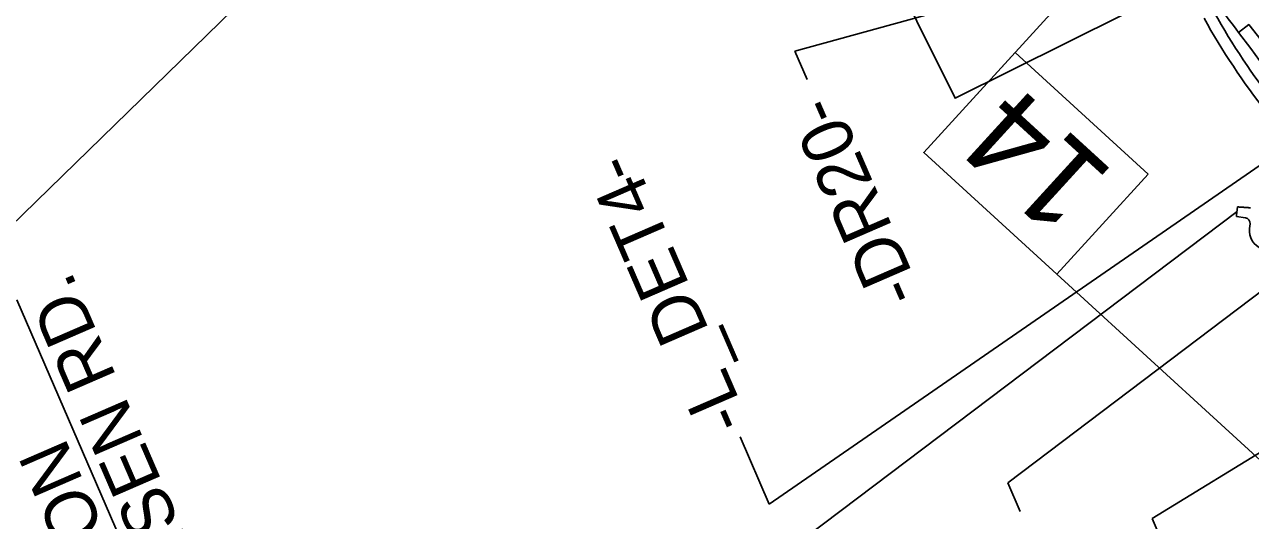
# Model space of a CAD drawing. Extents: x 442728 to 492797, y 479541 to 511293.
# Drawn here: x 474075 to 476357, y 500146 to 501068 of the extents above; entities that cross this region are included whole.
import ezdxf

# ---------------------------------------------------------------- set-up
doc = ezdxf.new("R2010")
doc.units = 0
for name, color, linetype in [('Prop DSN Text', 7, 'Continuous'), ('Prop Shade Light', 7, 'Continuous'), ('Sheet Plan Layout CELL', 7, 'Continuous')]:
    doc.layers.add(name, color=color, linetype=linetype)

msp = doc.modelspace()

# ---------------------------------------------------------------- linework, layer by layer
at = {"layer": 'Prop DSN Text'}
for p, q in [((475303.2, 501913.4), (474015.8, 500660.3)), ((475509.1, 501018.7), (476176.9, 501202.3)), ((475532.1, 500965.7), (475509.1, 501018.7)), ((475461.6, 500176.2), (476442.7, 500853.4)), ((476332.4, 500720.1), (475292.3, 499935.8)), ((475906, 500215.5), (476447.6, 500625.1)), ((474753.6, 498958.8), (474061, 500556.1)), ((476174.7, 500149.3), (476727.5, 500487.7)), ((475407.3, 500301.5), (475461.6, 500176.2)), ((475929, 500162.4), (475906, 500215.5)), ((476197.7, 500096.3), (476174.7, 500149.3))]:
    msp.add_line(p, q, dxfattribs=at)
at = {"layer": 'Prop Shade Light'}
for p, q in [((476335.4, 501053.5), (476354.4, 501068.2)), ((476331.4, 500711.2), (476348.2, 500708.6)), ((476356.6, 500697.6), (476355.6, 500689))]:
    msp.add_line(p, q, dxfattribs=at)
msp.add_lwpolyline([(476445.8, 500957.6), (476423, 500935.7), (476390.6, 500978.9), (476358.4, 501023.8), (476335.4, 501053.5), (476354.4, 501068.2), (476377.2, 501038.8), (476389.4, 501023.9), (476420.2, 500987.2), (476445.5, 500958)], close=True, dxfattribs=at)
msp.add_lwpolyline([(476333.4, 500729), (476331.6, 500713.3), (476331.4, 500711.2)], dxfattribs=at)
for centre, radius, start, end in [((478615.6, 502799.6), 2872, 214.9053, 217.4432), ((477416.9, 501716.9), 1311, 209.062, 218.2408), ((477416.9, 501716.9), 1289, 209.062, 218.2408), ((476346.7, 500698.7), 10, 353.6527, 81.3715), ((476391.4, 500685), 36, 173.6527, 250.4359)]:
    msp.add_arc(centre, radius, start, end, dxfattribs=at)
msp.add_spline([(476343.6, 500728.2), (476343.5, 500728.3), (476342.8, 500728.3), (476342.1, 500728.4), (476341.5, 500728.4), (476340.8, 500728.4), (476340.1, 500728.5), (476339.4, 500728.5), (476338.8, 500728.6), (476338.1, 500728.6), (476337.4, 500728.7), (476336.7, 500728.7), (476336.1, 500728.8), (476335.4, 500728.8), (476334.7, 500728.9), (476334, 500728.9), (476333.4, 500729)], degree=3, dxfattribs=at)
for points in [[(476345.5, 500728.1), (476345.3, 500728.1), (476345.1, 500728.2), (476344.8, 500728.2), (476344.6, 500728.2), (476344.4, 500728.2), (476344.2, 500728.2), (476344, 500728.2), (476343.8, 500728.2), (476343.6, 500728.2)], [(476346.1, 500728.1), (476345.9, 500728.1), (476345.7, 500728.1), (476345.5, 500728.1), (476345.5, 500728.1), (476345.5, 500728.1), (476345.5, 500728.1)], [(476348.9, 500727.9), (476348.7, 500727.9), (476348.4, 500727.9), (476348.2, 500727.9), (476348, 500727.9), (476347.8, 500728), (476347.5, 500728), (476347.3, 500728), (476347.1, 500728), (476346.9, 500728), (476346.6, 500728), (476346.4, 500728.1), (476346.2, 500728.1), (476346.2, 500728.1), (476346.2, 500728.1), (476346.1, 500728.1)], [(476350, 500727.8), (476349.9, 500727.8), (476349.7, 500727.8), (476349.6, 500727.8), (476349.3, 500727.9), (476349.1, 500727.9), (476348.9, 500727.9), (476348.9, 500727.9), (476348.9, 500727.9), (476348.9, 500727.9)], [(476352.3, 500727.7), (476352, 500727.7), (476351.8, 500727.7), (476351.6, 500727.7), (476351.4, 500727.7), (476351.1, 500727.7), (476350.9, 500727.7), (476350.7, 500727.8), (476350.5, 500727.8), (476350.2, 500727.8), (476350.2, 500727.8), (476350.1, 500727.8), (476350, 500727.8)], [(476357.5, 500727.3), (476357.3, 500727.3), (476357.1, 500727.3), (476357, 500727.3), (476356.7, 500727.3), (476356.5, 500727.4), (476356.3, 500727.4), (476356.1, 500727.4), (476355.8, 500727.4), (476355.6, 500727.4), (476355.4, 500727.4), (476355.2, 500727.5), (476354.9, 500727.5), (476354.7, 500727.5), (476354.5, 500727.5), (476354.3, 500727.5), (476354, 500727.5), (476353.8, 500727.5), (476353.6, 500727.6), (476353.4, 500727.6), (476353.2, 500727.6), (476352.9, 500727.6), (476352.7, 500727.6), (476352.5, 500727.6), (476352.3, 500727.7)]]:
    msp.add_open_spline(points, degree=3, dxfattribs=at)
at = {"layer": 'Sheet Plan Layout CELL'}
for points in [[(476747.8, 501398.6), (475807.6, 500931), (475306.6, 501938.3), (475306.7, 501938.4), (475139.7, 502274.1), (476079.9, 502741.6)], [(477564.9, 500593.5), (476856.6, 499818.3), (476026.1, 500577.2), (476026.1, 500577.2), (475749.3, 500830.1), (476457.6, 501605.3)], [(476167, 500789.6), (475919.2, 501016.1), (475749.3, 500830.1), (475997.1, 500603.7)]]:
    msp.add_lwpolyline(points, close=True, dxfattribs=at)

# ---------------------------------------------------------------- texts
at = {"layer": 'Prop DSN Text'}
for s, height, p in [('-DR20- ', 94.92, (475745.5, 500567)), ('-L_DET4- ', 94.92, (475423.6, 500330.5)), ('-Y10B- TAYLOR HENSEN RD.', 94.918, (474859.1, 499001.4)), ('BEGIN CONSTRUCTION', 94.918, (474727.1, 498970))]:
    msp.add_text(s, height=height, rotation=113.4424, dxfattribs=at).set_placement(p)
at = {"layer": 'Sheet Plan Layout CELL'}
msp.add_text('14', height=168.74, rotation=137.5752, dxfattribs=at).set_placement((476106.8, 500790.4))

doc.saveas('drawing.dxf')
